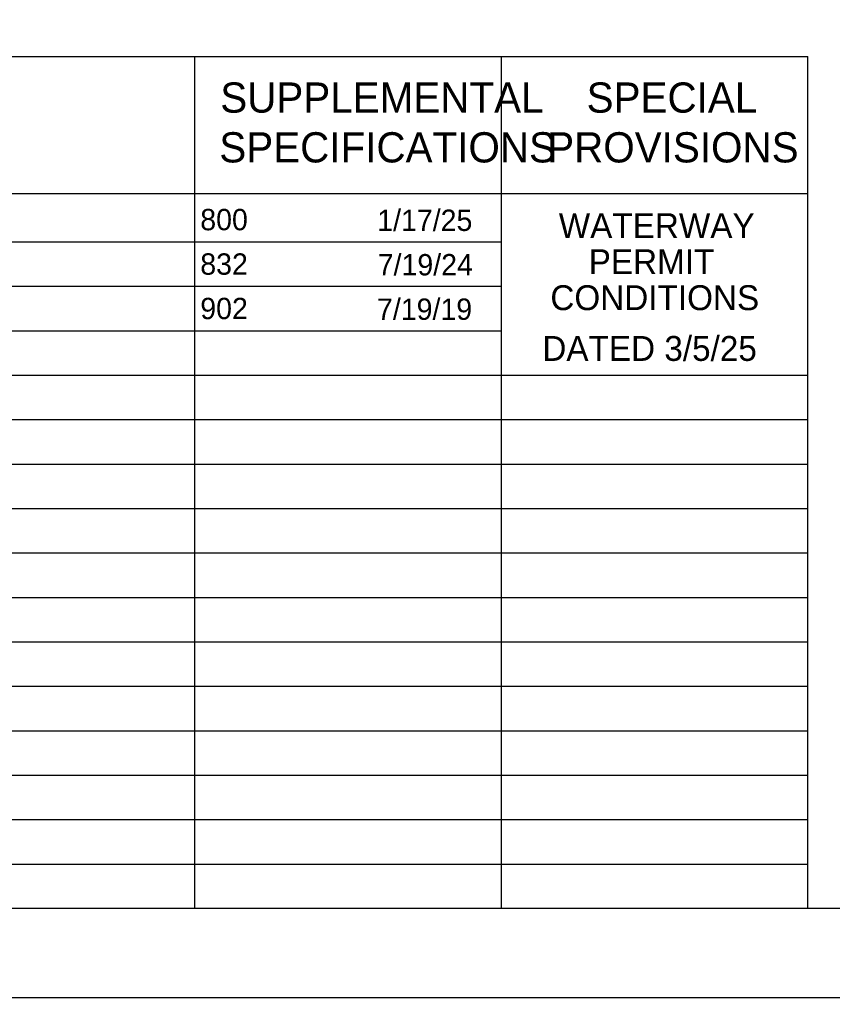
# Model space of a CAD drawing. Extents: x 0 to 34, y 0 to 22.
# Drawn here: x 20.26 to 24.84, y 0 to 5.5 of the extents above; entities that cross this region are included whole.
import ezdxf

# ---------------------------------------------------------------- set-up
doc = ezdxf.new("R2010")
doc.units = 0
for name, color, linetype in [('SH_Border', 7, 'Continuous'), ('SH_Cut_Line', 7, 'Continuous'), ('SH_Data', 7, 'Continuous'), ('SH_Text', 7, 'Continuous')]:
    doc.layers.add(name, color=color, linetype=linetype)

msp = doc.modelspace()

# ---------------------------------------------------------------- linework, layer by layer
at = {"layer": 'SH_Border'}
msp.add_lwpolyline([(1.5, 21.5), (33.5, 21.5), (33.5, 0.5), (1.5, 0.5)], close=True, dxfattribs=at)
at = {"layer": 'SH_Cut_Line'}
msp.add_lwpolyline([(0, 0), (34, 0), (34, 22), (0, 22)], close=True, dxfattribs=at)
at = {"layer": 'SH_Data'}
for p, q in [((11.25, 5.2917), (24.7, 5.2917)), ((21.25, 0.5), (21.25, 5.2917)), ((22.975, 0.5), (22.975, 5.2917)), ((24.7, 0.5), (24.7, 5.2917)), ((11.25, 4.5209), (24.7, 4.5209)), ((11.25, 4.25), (22.975, 4.25)), ((11.25, 4), (22.975, 4)), ((11.25, 3.75), (22.975, 3.75)), ((11.25, 3.5), (24.7, 3.5)), ((11.25, 3.25), (24.7, 3.25)), ((11.25, 3), (24.7, 3)), ((11.25, 2.75), (24.7, 2.75)), ((11.25, 2.5), (24.7, 2.5)), ((11.25, 2.25), (24.7, 2.25)), ((11.25, 2), (24.7, 2)), ((11.25, 1.75), (24.7, 1.75)), ((11.25, 1.5), (24.7, 1.5)), ((11.25, 1.25), (24.7, 1.25)), ((11.25, 1), (24.7, 1)), ((11.25, 0.75), (24.7, 0.75))]:
    msp.add_line(p, q, dxfattribs=at)

# ---------------------------------------------------------------- texts
at = {"layer": 'SH_Text'}
for s, height, p in [('SUPPLEMENTAL', 0.17, (21.3925, 4.9763)), ('SPECIAL', 0.17, (23.4542, 4.9763)), ('SPECIFICATIONS', 0.17, (21.3871, 4.6963)), ('PROVISIONS', 0.17, (23.2323, 4.6963)), ('800', 0.12, (21.28, 4.315)), ('1/17/25', 0.12, (22.2759, 4.3111)), ('WATERWAY ', 0.14, (23.2976, 4.2707)), ('832', 0.12, (21.28, 4.065)), ('7/19/24', 0.12, (22.2787, 4.0611)), ('PERMIT ', 0.14, (23.4659, 4.0682)), ('CONDITIONS', 0.14, (23.2501, 3.8657)), ('902', 0.12, (21.28, 3.815)), ('7/19/19', 0.12, (22.2746, 3.8111)), ('DATED 3/5/25', 0.14, (23.2051, 3.5802))]:
    msp.add_text(s, height=height, dxfattribs=at).set_placement(p)

doc.saveas('drawing.dxf')
